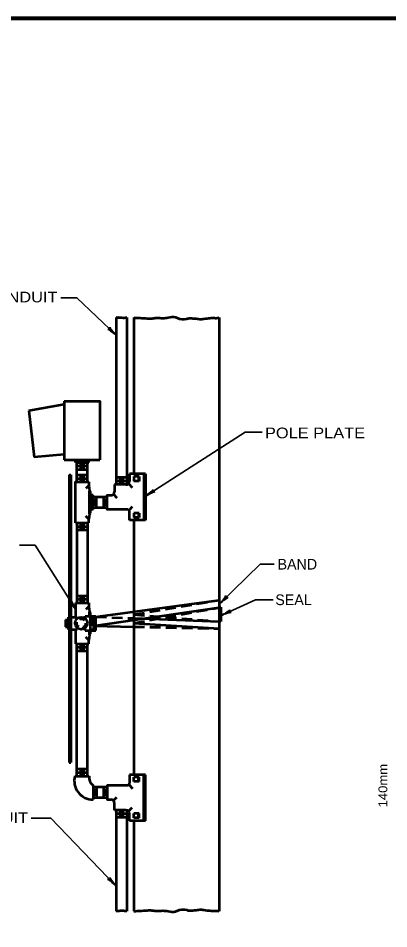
# Model space of a CAD drawing. Extents: x -31 to 825, y 0 to 544.
# Drawn here: x 204.1 to 329.4, y 230.5 to 537.9 of the extents above; entities that cross this region are included whole.
import ezdxf

# ---------------------------------------------------------------- set-up
doc = ezdxf.new("R2010")
doc.units = 0
doc.header["$LTSCALE"] = 1.2
doc.linetypes.add('MEDIUM_DASHED', pattern=[4.5, 3, -1.5])
doc.linetypes.add('SHORT_DASHED', pattern=[2.7, 1.5, -1.2])
doc.layers.add('1', color=7, linetype='Continuous', lineweight=53)

msp = doc.modelspace()

# ---------------------------------------------------------------- linework, layer by layer
at = {"layer": '1'}
for p, q in [((237.26, 436.827), (237.26, 380.427)), ((240.86, 436.827), (240.86, 380.427)), ((243.26, 436.827), (243.26, 384.027)), ((272.06, 436.827), (272.059, 341.427)), ((219.71, 407.427), (207.71, 405.327)), ((219.71, 408.627), (219.71, 388.827)), ((207.71, 405.327), (209.51, 389.727)), ((219.71, 390.627), (209.51, 389.727)), ((219.71, 388.827), (231.71, 388.827)), ((223.46, 387.927), (223.46, 388.827)), ((223.46, 387.927), (227.96, 387.927)), ((223.91, 381.327), (223.91, 387.927)), ((224.359, 387.927), (224.359, 388.827)), ((227.06, 387.927), (227.06, 388.827)), ((227.51, 381.327), (227.51, 387.927)), ((227.96, 387.927), (227.96, 388.827)), ((223.91, 386.727), (227.51, 386.727)), ((223.91, 385.527), (227.51, 385.527)), ((224.81, 387.327), (226.609, 387.327)), ((224.81, 386.127), (226.609, 386.127)), ((221.359, 383.727), (221.359, 286.595)), ((221.359, 383.727), (221.96, 383.727)), ((221.96, 383.727), (221.96, 286.595)), ((223.91, 383.727), (227.51, 383.727)), ((223.91, 382.527), (227.51, 382.527)), ((224.81, 383.127), (226.609, 383.127)), ((224.81, 381.927), (226.609, 381.927)), ((227.96, 381.327), (227.96, 380.127)), ((240.86, 382.827), (237.26, 382.827)), ((240.86, 381.627), (237.26, 381.627)), ((239.96, 382.227), (238.16, 382.227)), ((241.76, 384.027), (241.76, 381.627)), ((245.06, 383.127), (243.26, 383.127)), ((243.26, 383.127), (243.26, 381.627)), ((245.06, 381.627), (243.26, 381.627)), ((244.76, 383.127), (244.76, 381.627)), ((245.06, 383.127), (245.06, 381.627)), ((246.56, 384.027), (246.56, 368.427)), ((247.16, 384.027), (247.16, 368.427)), ((227.96, 380.127), (227.035, 379.102)), ((227.96, 380.127), (228.26, 378.327)), ((228.26, 370.527), (228.26, 378.327)), ((228.26, 378.327), (228.56, 378.027)), ((240.56, 380.427), (236.66, 380.427)), ((236.66, 380.427), (236.66, 378.027)), ((239.96, 381.027), (238.16, 381.027)), ((241.47, 380.799), (242.653, 379.489)), ((228.56, 370.827), (228.56, 378.027)), ((229.46, 376.827), (228.56, 376.827)), ((229.46, 372.027), (229.46, 376.827)), ((234.26, 376.227), (229.46, 376.227)), ((230.06, 373.227), (230.06, 375.627)), ((230.66, 372.627), (230.66, 376.227)), ((233.06, 372.627), (233.06, 376.227)), ((233.66, 373.227), (233.66, 375.627)), ((236.318, 377.165), (237.5, 375.982)), ((229.46, 372.027), (228.56, 372.027)), ((234.26, 372.627), (229.46, 372.627)), ((241.639, 371.8), (242.751, 373.097)), ((227.96, 368.727), (227.035, 369.752)), ((228.26, 370.527), (227.96, 368.727)), ((228.26, 370.527), (228.56, 370.827)), ((241.76, 368.427), (241.76, 371.427)), ((243.26, 370.827), (243.26, 369.327)), ((245.06, 370.827), (243.26, 370.827)), ((245.06, 369.327), (243.26, 369.327)), ((244.76, 370.827), (244.76, 369.327)), ((245.06, 370.827), (245.06, 369.327)), ((223.46, 367.527), (227.96, 367.527)), ((223.91, 367.527), (223.91, 340.527)), ((223.91, 366.327), (227.51, 366.327)), ((224.81, 366.927), (226.609, 366.927)), ((227.51, 367.527), (227.51, 340.527)), ((227.96, 367.527), (227.96, 368.727)), ((247.16, 368.427), (241.76, 368.427)), ((243.259, 368.427), (243.259, 282.496)), ((223.91, 365.127), (227.51, 365.127)), ((224.81, 365.727), (226.609, 365.727)), ((223.91, 342.927), (227.51, 342.927)), ((223.91, 341.727), (227.51, 341.727)), ((224.81, 342.327), (226.609, 342.327)), ((229.46, 335.727), (272.059, 341.427)), ((272.059, 341.427), (272.059, 331.827)), ((223.46, 340.527), (227.96, 340.527)), ((223.46, 340.527), (223.46, 335.727)), ((224.81, 341.127), (226.609, 341.127)), ((227.96, 339.327), (227.035, 338.302)), ((227.96, 340.527), (227.96, 339.327)), ((227.96, 339.327), (228.26, 337.527)), ((229.76, 332.727), (272.059, 338.938)), ((272.659, 339.026), (272.059, 339.026)), ((272.659, 339.026), (272.659, 334.227)), ((221.06, 335.727), (221.06, 331.527)), ((221.06, 335.727), (221.359, 335.727)), ((221.96, 335.727), (224.06, 335.727)), ((224.06, 335.727), (224.06, 335.207)), ((226.76, 336.027), (230.359, 336.027)), ((226.76, 335.268), (226.76, 336.027)), ((228.26, 337.527), (228.56, 337.227)), ((228.26, 336.027), (228.26, 337.527)), ((228.56, 336.027), (228.56, 337.227)), ((228.56, 331.527), (228.56, 335.727)), ((228.56, 335.727), (229.46, 335.727)), ((229.46, 332.727), (229.46, 335.727)), ((230.359, 335.847), (230.359, 336.027)), ((243.259, 335.3), (272.059, 334.227)), ((220.16, 334.827), (220.16, 332.427)), ((220.16, 334.827), (221.06, 334.827)), ((220.16, 334.227), (221.06, 334.227)), ((220.16, 333.027), (221.06, 333.027)), ((220.16, 332.427), (221.06, 332.427)), ((224.06, 331.527), (224.06, 332.052)), ((229.46, 332.727), (229.76, 332.727)), ((229.76, 331.527), (229.76, 332.727)), ((229.76, 332.727), (243.259, 332.44)), ((229.76, 332.727), (229.855, 332.296)), ((230.359, 331.227), (230.359, 332.714)), ((243.252, 333.665), (272.059, 331.827)), ((272.659, 334.227), (272.059, 334.227)), ((221.06, 331.527), (221.359, 331.527)), ((221.96, 331.527), (224.06, 331.527)), ((223.46, 331.527), (223.46, 326.727)), ((226.76, 331.227), (226.76, 331.992)), ((226.76, 331.227), (230.359, 331.227)), ((228.26, 329.727), (227.96, 327.927)), ((228.26, 329.727), (228.26, 331.227)), ((228.26, 329.727), (228.56, 330.027)), ((228.56, 331.527), (229.76, 331.527)), ((228.56, 330.027), (228.56, 331.227)), ((272.059, 331.827), (272.059, 236.427)), ((223.46, 326.727), (227.96, 326.727)), ((223.91, 282.027), (223.91, 326.727)), ((224.81, 326.127), (226.609, 326.127)), ((227.96, 327.927), (227.035, 328.952)), ((227.51, 282.027), (227.51, 326.727)), ((227.96, 326.727), (227.96, 327.927)), ((223.91, 325.527), (227.51, 325.527)), ((223.91, 324.327), (227.51, 324.327)), ((224.81, 324.927), (226.609, 324.927)), ((221.359, 286.595), (221.96, 286.595)), ((223.91, 284.427), (227.51, 284.427)), ((223.91, 283.227), (227.51, 283.227)), ((224.81, 283.827), (226.609, 283.827)), ((223.31, 282.027), (228.109, 282.027)), ((224.81, 282.627), (226.609, 282.627)), ((247.16, 282.496), (241.76, 282.496)), ((241.76, 282.496), (241.76, 279.496)), ((245.06, 281.702), (243.26, 281.702)), ((243.26, 280.202), (243.26, 281.702)), ((245.06, 280.202), (243.26, 280.202)), ((244.76, 280.202), (244.76, 281.702)), ((245.06, 280.202), (245.06, 281.702)), ((246.56, 266.896), (246.56, 282.496)), ((247.16, 266.896), (247.16, 282.496)), ((234.217, 278.307), (229.417, 278.307)), ((229.46, 278.896), (229.46, 274.096)), ((230.017, 277.707), (230.017, 275.307)), ((230.617, 278.307), (230.617, 274.707)), ((233.017, 278.307), (233.017, 274.707)), ((233.617, 277.707), (233.617, 275.307)), ((241.639, 279.124), (242.751, 277.826)), ((234.217, 274.707), (229.417, 274.707)), ((236.318, 273.758), (237.5, 274.941)), ((236.66, 270.496), (236.66, 272.896)), ((241.47, 270.124), (242.653, 271.434)), ((240.56, 270.496), (236.66, 270.496)), ((237.259, 270.496), (237.259, 236.427)), ((240.859, 269.296), (237.259, 269.296)), ((240.859, 268.096), (237.259, 268.096)), ((239.959, 269.896), (238.159, 269.896)), ((239.959, 268.696), (238.159, 268.696)), ((240.859, 270.496), (240.859, 236.427)), ((241.76, 266.896), (241.76, 269.296)), ((243.26, 267.902), (243.26, 269.402)), ((245.06, 269.402), (243.26, 269.402)), ((245.06, 267.902), (243.26, 267.902)), ((244.76, 267.902), (244.76, 269.402)), ((245.06, 267.902), (245.06, 269.402)), ((247.16, 266.896), (241.76, 266.896)), ((243.259, 266.896), (243.259, 236.427))]:
    msp.add_line(p, q, dxfattribs=at)
at = {"layer": '1', "linetype": 'MEDIUM_DASHED'}
for p, q in [((243.252, 336.528), (272.059, 341.427)), ((243.252, 333.665), (272.059, 338.938)), ((230.353, 335.781), (243.259, 335.3)), ((230.359, 332.714), (230.359, 335.847)), ((243.252, 336.528), (272.059, 334.227)), ((243.259, 332.44), (272.059, 331.827))]:
    msp.add_line(p, q, dxfattribs=at)
at = {"layer": '1', "lineweight": 158}
msp.add_lwpolyline([(818.018, 537.903), (26.318, 537.803), (26.418, 11.803)], dxfattribs=at)
at = {"layer": '1', "lineweight": 35}
for points in [[(237.26, 430.843), (223.998, 443.507), (218.574, 443.507)], [(247.203, 376.532), (280.89, 398.088), (286.564, 398.088)], [(223.37, 338.55), (209.837, 359.947), (204.599, 359.947)], [(272.174, 340.191), (285.894, 353.541), (290.692, 353.541)], [(272.774, 336.291), (284.394, 341.541), (290.317, 341.541)], [(237.149, 245.007), (215.151, 267.819), (208.491, 267.819)]]:
    msp.add_lwpolyline(points, dxfattribs=at)
at = {"layer": '1'}
for points in [[(219.71, 408.627), (231.71, 408.627), (231.71, 388.827)], [(223.46, 367.527), (223.46, 381.327), (227.96, 381.327)], [(247.16, 384.027), (246.56, 384.027), (241.76, 384.027)], [(241.16, 372.027), (234.26, 372.027), (234.26, 376.827), (235.46, 376.827)], [(241.16, 278.896), (234.26, 278.896), (234.26, 274.096), (235.46, 274.096)]]:
    msp.add_lwpolyline(points, dxfattribs=at)
msp.add_circle((225.445, 333.63), 2.1, dxfattribs=at)
at = {"layer": '1', "linetype": 'SHORT_DASHED'}
msp.add_circle((225.445, 333.63), 1.5, dxfattribs=at)
at = {"layer": '1'}
for centre, radius, start, end in [((240.56, 381.627), 1.2, 270, 0), ((235.46, 378.027), 1.2, 270, 0), ((241.16, 371.427), 0.6, 0, 90), ((229.411, 280.409), 6.312, 165.14748, 270.43944), ((231.302, 281.547), 3.228, 171.4535, 235.2032), ((241.16, 279.496), 0.6, 270, 0), ((235.46, 272.896), 1.2, 0, 90), ((240.56, 269.296), 1.2, 0, 90)]:
    msp.add_arc(centre, radius, start, end, dxfattribs=at)
at = {"layer": '1', "lineweight": 40}
for centre, major_axis, ratio, start_param, end_param in [((236.463, 431.955), (-1.379, 1.608), 0.07063, 6.2823074, 8.5597026), ((236.084, 431.508), (1.679, -1.344), 0.122415, 0.8963533, 3.1415927), ((248.127, 377.517), (-1.704, -1.313), 0.122415, 0.8963533, 3.1415927), ((248.127, 377.517), (-1.704, -1.313), 0.122415, 0.8963533, 3.1415927), ((248.472, 377.043), (1.889, 0.958), 0.07063, 6.2823074, 8.5597026), ((248.472, 377.043), (1.889, 0.958), 0.07063, 6.2823074, 8.5597026), ((222.866, 339.822), (-0.948, 1.894), 0.07063, 6.2823074, 8.5597026), ((272.881, 341.342), (-1.405, -1.629), 0.122415, 0.8963533, 3.1415927), ((272.881, 341.342), (-1.405, -1.629), 0.122415, 0.8963533, 3.1415927), ((273.314, 340.947), (1.658, 1.319), 0.07063, 6.2823074, 8.5597026), ((273.314, 340.947), (1.658, 1.319), 0.07063, 6.2823074, 8.5597026), ((222.39, 339.479), (1.304, -1.711), 0.122415, 0.8963533, 3.1415927), ((273.83, 337.133), (-1.876, -1.053), 0.122415, 0.8963533, 3.1415927), ((273.83, 337.133), (-1.876, -1.053), 0.122415, 0.8963533, 3.1415927), ((274.103, 336.613), (-2.008, -0.676), 0.07063, 3.1407148, 5.41811), ((274.103, 336.613), (-2.008, -0.676), 0.07063, 3.1407148, 5.41811), ((236.001, 245.719), (1.622, -1.412), 0.122415, 0.8963533, 3.1415927), ((236.001, 245.719), (1.622, -1.412), 0.122415, 0.8963533, 3.1415927), ((236.398, 246.151), (-1.311, 1.664), 0.07063, 6.2823074, 8.5597026), ((236.398, 246.151), (-1.311, 1.664), 0.07063, 6.2823074, 8.5597026)]:
    msp.add_ellipse(centre, major_axis=major_axis, ratio=ratio, start_param=start_param, end_param=end_param, dxfattribs=at)
at = {"layer": '1'}
for points in [[(237.26, 436.827), (237.667, 436.925), (238.185, 436.836), (238.649, 436.818), (239.612, 436.783), (239.987, 436.765), (240.611, 436.836), (240.86, 436.827)], [(243.26, 436.827), (245.395, 436.705), (247.722, 436.569), (249.364, 436.569), (250.597, 436.705), (251.965, 436.705), (254.019, 436.705), (254.84, 436.842), (257.304, 436.979), (257.852, 436.705), (261.137, 436.432), (261.548, 436.569), (263.191, 436.569), (264.697, 436.432), (265.518, 436.295), (266.887, 436.432), (267.982, 436.569), (269.762, 436.705), (270.172, 436.705), (271.404, 436.705), (272.06, 436.827)], [(243.259, 236.427), (245.393, 236.548), (247.721, 236.685), (249.363, 236.685), (250.595, 236.548), (251.964, 236.548), (254.018, 236.548), (254.839, 236.411), (257.303, 236.274), (257.851, 236.548), (261.136, 236.822), (261.547, 236.685), (263.19, 236.685), (264.696, 236.822), (265.517, 236.959), (266.886, 236.822), (267.981, 236.685), (269.761, 236.548), (270.171, 236.548), (271.403, 236.548), (272.059, 236.427)], [(237.259, 236.427), (237.992, 236.537), (238.634, 236.588), (239.199, 236.639), (239.738, 236.588), (240.431, 236.562), (240.859, 236.427)]]:
    msp.add_spline(points, degree=3, dxfattribs=at)

# ---------------------------------------------------------------- texts
at = {"layer": '1', "width": 1.15}
for s, p in [('31.8mm CONDUIT', (170.679, 441.961)), ('POLE PLATE', (287.541, 396.082)), ('31.8mm CONDUIT', (160.736, 266.138))]:
    msp.add_text(s, height=3.6, dxfattribs=at).set_placement(p)
at = {"layer": '1'}
for s, p in [('BAND', (291.798, 351.759)), ('SEAL', (291.034, 339.75))]:
    msp.add_text(s, height=3.6, dxfattribs=at).set_placement(p)
at = {"layer": '1', "width": 1.1}
msp.add_text('140mm', height=3, rotation=90, dxfattribs=at).set_placement((328.899, 271.436))

doc.saveas('drawing.dxf')
